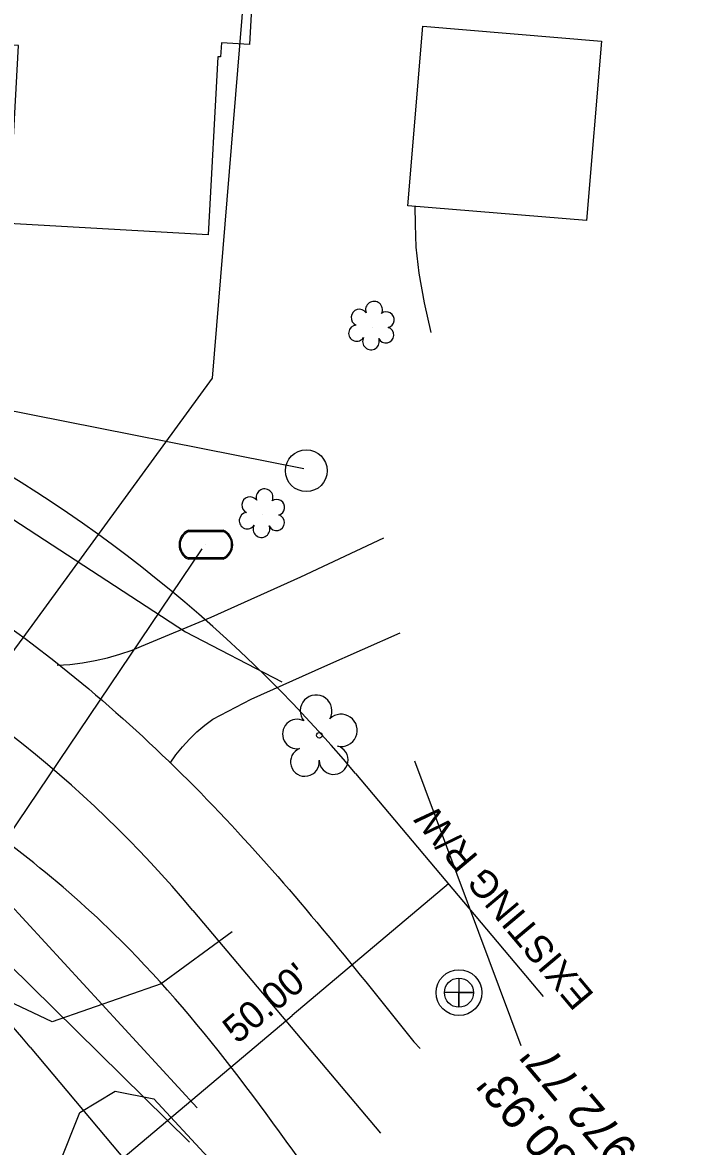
# Model space of a CAD drawing. Extents: x 1614427 to 1617186, y 896524 to 905462.
# Drawn here: x 1616898 to 1616978, y 901571.1 to 901703.2 of the extents above; entities that cross this region are included whole.
import ezdxf

# ---------------------------------------------------------------- set-up
doc = ezdxf.new("R2010")
doc.units = 0
for name, color, linetype in [('Exist Building', 7, 'Continuous'), ('Exist Building Metal Canopy', 7, 'Continuous'), ('Exist Horizontal Alignment', 7, 'Continuous'), ('Exist Right of Way Line', 7, 'Continuous'), ('Exist Right of Way Line Text', 7, 'Continuous'), ('Exist Right of Way Width CELL', 7, 'Continuous'), ('Exist Roads EOP', 7, 'Continuous'), ('Exist Roads EOP Other', 7, 'Continuous'), ('Exist Roads Soil', 7, 'Continuous'), ('Exist Utilities Gas UG Line SUE LOS B', 7, 'Continuous'), ('Exist Utilities Other Pole CELL', 7, 'Continuous'), ('Exist Utilities Power UG Cable SUE LOS D', 7, 'Continuous'), ('Exist Utilities Sanitary Sewer Manhole CELL', 7, 'Continuous'), ('Exist Utilities Sanitary Sewer Manhole Text', 7, 'Continuous'), ('Exist Utilities Sanitary Sewer UG Line Invert Elevation', 7, 'Continuous'), ('Exist Utilities Telephone UG Cable SUE LOS B', 7, 'Continuous'), ('Exist Utilities TV UG Cable SUE LOS B', 7, 'Continuous'), ('Exist Utilities Water Meter CELL', 7, 'Continuous'), ('Exist Utilities Water UG Line SUE LOS B', 7, 'Continuous'), ('Exist Vegetation Shrub CELL', 7, 'Continuous'), ('Exist Vegetation Tree CELL', 7, 'Continuous'), ('Exist Vegetation Woods Line', 7, 'Continuous')]:
    doc.layers.add(name, color=color, linetype=linetype)

# ---------------------------------------------------------------- blocks, each defined once
blk = doc.blocks.new('EXIST UTILITIES SANITARY SEWER MANHOLE')
at = {"layer": 'Exist Utilities Sanitary Sewer Manhole CELL'}
blk.add_lwpolyline([(0, 0.03425), (0, -0.03425), (0, 0), (0.03425, 0), (-0.03425, 0)], dxfattribs=at)
for radius in [0.05389, 0.03425]:
    blk.add_circle((0, 0), radius, dxfattribs=at)
blk = doc.blocks.new('EXIST UTILITIES WATER METER')
at = {"layer": 'Exist Utilities Water Meter CELL'}
blk.add_line((0, 0), (0, 0), dxfattribs=at)
for points in [[(-0.0408, 0.034), (0.0408, 0.034)], [(-0.0408, 0.0312), (0.0408, 0.0312)], [(0.0408, -0.0312), (-0.0413, -0.0312)], [(0.0408, -0.034), (-0.0413, -0.034)]]:
    blk.add_lwpolyline(points, dxfattribs=at)
for centre, radius, start, end in [((-0.0261, -0.0001), 0.0371, 113.178, 245.9794), ((-0.0259, -0.0001), 0.0347, 115.3009, 243.7824), ((0.0259, 0), 0.0371, 293.6483, 66.3084), ((0.0261, 0), 0.0345, 295.1272, 64.8728)]:
    blk.add_arc(centre, radius, start, end, dxfattribs=at)

msp = doc.modelspace()

# ---------------------------------------------------------------- linework, layer by layer
at = {"layer": 'Exist Building'}
msp.add_lwpolyline([(1616923.85, 901744.74), (1616922.23, 901715.69), (1616925.54, 901715.51), (1616924.71, 901700.65), (1616921.39, 901700.83), (1616921.29, 901699.18), (1616920.99, 901699.2), (1616919.82, 901678.27), (1616896.38, 901679.58), (1616897.55, 901700.51), (1616885.12, 901701.2), (1616885.51, 901708.11), (1616884.01, 901708.19), (1616885.27, 901730.86), (1616891.72, 901730.5), (1616892.61, 901746.47), (1616894.05, 901746.38), (1616894.61, 901756.38), (1616910.19, 901755.51), (1616909.64, 901745.54)], close=True, dxfattribs=at)
at = {"layer": 'Exist Building Metal Canopy'}
msp.add_lwpolyline([(1616943.3, 901681.68), (1616945.07, 901702.78), (1616966.08, 901701.02), (1616964.31, 901679.92)], close=True, dxfattribs=at)
at = {"layer": 'Exist Horizontal Alignment'}
msp.add_line((1616918.05, 901598.82), (1616940.09, 901572.62), dxfattribs=at)
msp.add_arc((1616808.43, 901506.62), 143.24, 40.0666, 87.5, dxfattribs=at)
at = {"layer": 'Exist Right of Way Line'}
for p, q in [((1616937.18, 901614.91), (1616959.22, 901588.71)), ((1616898.92, 901582.73), (1616920.95, 901556.52))]:
    msp.add_line(p, q, dxfattribs=at)
for radius in [168.24, 118.24]:
    msp.add_arc((1616808.43, 901506.62), radius, 40.0666, 87.5, dxfattribs=at)
at = {"layer": 'Exist Right of Way Width CELL'}
for p in [(1616948.1, 901601.93), (1616909.83, 901569.74)]:
    msp.add_line(p, (1616929.72, 901586.47), dxfattribs=at)
at = {"layer": 'Exist Roads EOP'}
msp.add_line((1616944.04, 901583.35), (1616944.76, 901582.57), dxfattribs=at)
for points in [[(1616824.78, 901658.44), (1616864.78, 901649.17), (1616898.31, 901630.78), (1616923.33, 901608.03), (1616944.04, 901583.35)], [(1616935.21, 901562.99), (1616908.71, 901596.12), (1616886.25, 901614), (1616856.21, 901630.5), (1616813.66, 901640.53)]]:
    msp.add_spline(points, degree=3, dxfattribs=at)
at = {"layer": 'Exist Roads EOP Other'}
for points in [[(1616902.07, 901627.64), (1616903.57, 901627.74), (1616905.06, 901627.93), (1616906.55, 901628.19), (1616908.01, 901628.53), (1616909.46, 901628.95), (1616910.89, 901629.43), (1616912, 901629.87), (1616920.21, 901633.3), (1616930.74, 901638.03), (1616940.5, 901642.64)], [(1616915.35, 901616.12), (1616916.05, 901617.11), (1616916.81, 901618.07), (1616917.63, 901618.97), (1616918.5, 901619.81), (1616919.43, 901620.6), (1616920.4, 901621.32), (1616924.91, 901623.67), (1616933.55, 901627.55), (1616942.42, 901631.47)]]:
    msp.add_lwpolyline(points, dxfattribs=at)
at = {"layer": 'Exist Roads Soil'}
msp.add_lwpolyline([(1616946.08, 901666.76), (1616945.29, 901670.27), (1616944.67, 901673.75), (1616944.3, 901676.79), (1616944.21, 901679.45), (1616944.18, 901681.61)], dxfattribs=at)
at = {"layer": 'Exist Utilities Gas UG Line SUE LOS B'}
for points in [[(1616881.11, 901607.83), (1616898.08, 901630.87), (1616920.35, 901661.39), (1616926.07, 901730.99), (1616937.09, 901731.49)], [(1616917.65, 901571.58), (1616880.41, 901608.23), (1616849.92, 901623.71), (1616822.5, 901631.75), (1616770.94, 901633.74), (1616722.82, 901632.98), (1616657.05, 901629.46), (1616645.52, 901627.05), (1616601.03, 901635.6)]]:
    msp.add_lwpolyline(points, dxfattribs=at)
at = {"layer": 'Exist Utilities Other Pole CELL'}
msp.add_circle((1616931.38, 901650.52), 2.46, dxfattribs=at)
at = {"layer": 'Exist Utilities Power UG Cable SUE LOS D'}
msp.add_line((1616931.07, 901650.73), (1616691.03, 901698.22), dxfattribs=at)
at = {"layer": 'Exist Utilities Telephone UG Cable SUE LOS B'}
msp.add_line((1616956.65, 901582.9), (1616944.16, 901616.38), dxfattribs=at)
msp.add_lwpolyline([(1616922.67, 901596.29), (1616914.32, 901590.19), (1616901.49, 901585.7), (1616852.94, 901608.68), (1616851.1, 901602.28)], dxfattribs=at)
at = {"layer": 'Exist Utilities TV UG Cable SUE LOS B'}
msp.add_lwpolyline([(1616668.72, 901703.15), (1616667.3, 901698.9), (1616667.84, 901692.04), (1616673.22, 901687.1), (1616695.23, 901680.57), (1616753.52, 901674.2), (1616810.66, 901673.54), (1616837.01, 901667.23), (1616870.02, 901657.45), (1616896.87, 901644.83), (1616917.17, 901631.58), (1616928.5, 901625.7)], dxfattribs=at)
at = {"layer": 'Exist Utilities Water UG Line SUE LOS B'}
msp.add_line((1616893.33, 901603.1), (1616919.13, 901641.33), dxfattribs=at)
msp.add_lwpolyline([(1616655.63, 901639.2), (1616655.48, 901638.95), (1616664.15, 901638.64), (1616712.65, 901640.23), (1616757.87, 901639.52), (1616821.96, 901637.35), (1616876.05, 901621.78), (1616918.56, 901575.59)], dxfattribs=at)
at = {"layer": 'Exist Vegetation Shrub CELL'}
for p, q in [((1616939.11, 901667.4), (1616939.11, 901667.4)), ((1616926.24, 901645.34), (1616926.24, 901645.34))]:
    msp.add_line(p, q, dxfattribs=at)
for centre, radius, start, end in [((1616939.34, 901669.44), 0.99, 334.8391, 200.4717), ((1616937.62, 901668.53), 0.968, 35.8908, 245.4216), ((1616940.78, 901668.27), 0.929, 284.4567, 126.0861), ((1616937.31, 901666.7), 0.955, 95.1099, 327.9534), ((1616940.74, 901666.47), 0.937, 204.9913, 73.4601), ((1616938.98, 901665.72), 0.984, 151.2797, 21.387), ((1616926.47, 901647.39), 0.99, 334.8391, 200.4717), ((1616924.76, 901646.47), 0.968, 35.8908, 245.4216), ((1616927.91, 901646.21), 0.929, 284.4567, 126.0861), ((1616924.44, 901644.64), 0.955, 95.1099, 327.9534), ((1616927.87, 901644.42), 0.937, 204.9913, 73.4601), ((1616926.11, 901643.66), 0.984, 151.2797, 21.387)]:
    msp.add_arc(centre, radius, start, end, dxfattribs=at)
at = {"layer": 'Exist Vegetation Tree CELL'}
msp.add_line((1616932.92, 901619.41), (1616932.92, 901619.41), dxfattribs=at)
msp.add_circle((1616932.92, 901619.41), 0.326, dxfattribs=at)
for centre, radius, start, end in [((1616932.53, 901622.28), 1.86, 330.1651, 219.7134), ((1616930.31, 901619.56), 1.73, 62.6636, 279.3457), ((1616935.47, 901619.99), 1.9, 257.1011, 134.1999), ((1616931.21, 901616.28), 1.69, 111.5671, 6.231), ((1616934.59, 901616.51), 1.7, 181.2822, 74.56)]:
    msp.add_arc(centre, radius, start, end, dxfattribs=at)
at = {"layer": 'Exist Vegetation Woods Line'}
msp.add_lwpolyline([(1616922.16, 901518.5), (1616915.99, 901528.53), (1616914.15, 901539.06), (1616909.09, 901548.41), (1616903.87, 901557.88), (1616902.27, 901568.88), (1616904.76, 901575.06), (1616908.91, 901577.57), (1616913.46, 901576.67), (1616919.85, 901569.77), (1616930.06, 901551.78)], dxfattribs=at)

# ---------------------------------------------------------------- block references
at = {"layer": 'Exist Utilities Sanitary Sewer Manhole CELL', "xscale": 50, "yscale": 50}
msp.add_blockref('EXIST UTILITIES SANITARY SEWER MANHOLE', (1616949.33, 901589.15), dxfattribs=at)
at = {"layer": 'Exist Utilities Water Meter CELL', "xscale": 50, "yscale": 50}
msp.add_blockref('EXIST UTILITIES WATER METER', (1616919.57, 901641.82), dxfattribs=at)

# ---------------------------------------------------------------- texts
at = {"layer": 'Exist Right of Way Line Text'}
msp.add_text('EXISTING R/W', height=3.2, rotation=130.0666, dxfattribs=at).set_placement((1616965.34, 901588.89))
at = {"layer": 'Exist Right of Way Width CELL'}
msp.add_text("50.00'", height=3.2, rotation=40.0666, dxfattribs=at).set_placement((1616923.26, 901583.03))
at = {"layer": 'Exist Utilities Sanitary Sewer Manhole Text'}
msp.add_text("TOP=980.93'", height=4, rotation=130.0666, dxfattribs=at).set_placement((1616974.55, 901556.53))
at = {"layer": 'Exist Utilities Sanitary Sewer UG Line Invert Elevation'}
msp.add_text("INV=972.77'", height=4, rotation=130.0666, dxfattribs=at).set_placement((1616978.29, 901561.5))

doc.saveas('drawing.dxf')
